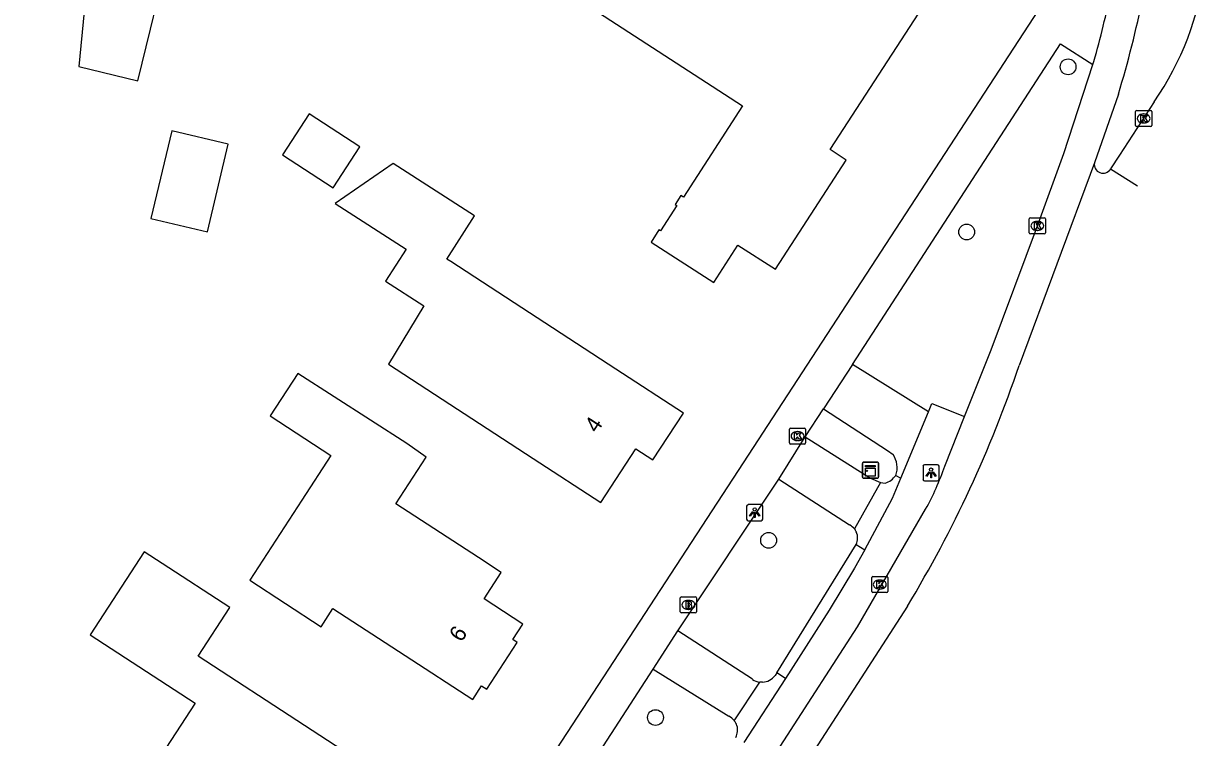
# Model space of a CAD drawing. Extents: x 161141 to 161601, y 381708 to 382245.
# Drawn here: x 161517.1 to 161590.2, y 382082.4 to 382126.6 of the extents above; entities that cross this region are included whole.
import ezdxf

# ---------------------------------------------------------------- set-up
doc = ezdxf.new("R2010")
doc.units = 0
for name, color, linetype in [('IMGEO_Boom', 7, 'Continuous'), ('IMGEO_Brandkraan', 7, 'Continuous'), ('IMGEO_Kast', 7, 'Continuous'), ('IMGEO_Kolk', 7, 'Continuous'), ('IMGEO_Lichtpunt', 7, 'Continuous'), ('IMGEO_Pand', 7, 'Continuous'), ('IMGEO_Pand_nummerreeks', 7, 'Continuous'), ('IMGEO_Parkeervlak_open', 7, 'Continuous'), ('IMGEO_Rijbaan_lokaal_gesloten', 7, 'Continuous'), ('IMGEO_Rijbaan_lokaal_open', 7, 'Continuous'), ('IMGEO_Voetpad_open', 7, 'Continuous')]:
    doc.layers.add(name, color=color, linetype=linetype)

msp = doc.modelspace()

# ---------------------------------------------------------------- linework, layer by layer
at = {"layer": 'IMGEO_Boom'}
for centre in [(161581.734, 382123.901), (161575.455, 382113.672), (161563.196, 382094.579), (161556.197, 382083.607)]:
    msp.add_circle(centre, 0.489, dxfattribs=at)
at = {"layer": 'IMGEO_Brandkraan'}
for p, q in [((161557.732, 382090.159), (161557.732, 382091.011)), ((161557.807, 382091.085), (161558.659, 382091.085)), ((161558.733, 382091.011), (161558.733, 382090.159)), ((161558.243, 382090.305), (161558.218, 382090.305)), ((161558.22, 382090.865), (161558.245, 382090.865)), ((161558.659, 382090.085), (161557.807, 382090.085))]:
    msp.add_line(p, q, dxfattribs=at)
for points in [[(161557.732, 382090.159), (161557.732, 382091.011)], [(161557.807, 382091.085), (161558.659, 382091.085)], [(161558.733, 382091.011), (161558.733, 382090.159)], [(161558.08, 382090.785), (161558.08, 382090.385), (161558.293, 382090.385)], [(161558.311, 382090.785), (161558.08, 382090.785)], [(161558.259, 382090.704), (161558.205, 382090.704), (161558.205, 382090.628)], [(161558.205, 382090.628), (161558.258, 382090.628)], [(161558.267, 382090.552), (161558.205, 382090.552), (161558.205, 382090.471)], [(161558.205, 382090.471), (161558.267, 382090.471)], [(161558.659, 382090.085), (161557.807, 382090.085)]]:
    msp.add_lwpolyline(points, dxfattribs=at)
for centre, radius, start, end in [((161557.809, 382091.009), 0.0765, 91.55205, 178.44795), ((161557.809, 382091.009), 0.0765, 91.55205, 178.44795), ((161558.657, 382091.009), 0.0765, 1.55205, 88.44795), ((161558.657, 382091.009), 0.0765, 1.55205, 88.44795), ((161557.809, 382090.161), 0.0765, 181.55205, 268.44795), ((161557.809, 382090.161), 0.0765, 181.55205, 268.44795), ((161558.26, 382090.666), 0.0379, 267.82845, 90.93552), ((161558.268, 382090.511), 0.0404, 269.87594, 90.50774), ((161558.299, 382090.636), 0.251, 268.66757, 293.53466), ((161558.315, 382090.64), 0.145, 59.4692, 91.53667), ((161558.34, 382090.687), 0.0922, 285.51372, 58.15012), ((161558.345, 382090.495), 0.105, 301.31148, 78.98903), ((161558.657, 382090.161), 0.0765, 271.55205, 358.44795), ((161558.657, 382090.161), 0.0765, 271.55205, 358.44795)]:
    msp.add_arc(centre, radius, start, end, dxfattribs=at)
for centre, major_axis, ratio, start_param, end_param in [((161558.219, 382090.585), (-0.387, 0.002), 0.722429, 4.712389, 7.853982), ((161558.244, 382090.585), (-0.39, 0.002), 0.717154, 1.570796, 4.712389)]:
    msp.add_ellipse(centre, major_axis=major_axis, ratio=ratio, start_param=start_param, end_param=end_param, dxfattribs=at)
at = {"layer": 'IMGEO_Kast'}
for p, q in [((161569.001, 382098.502), (161569.001, 382099.343)), ((161569.001, 382099.343), (161569.001, 382098.502)), ((161569.076, 382099.427), (161569.917, 382099.427)), ((161569.917, 382099.427), (161569.076, 382099.427)), ((161570.001, 382099.352), (161570.001, 382098.511)), ((161570.001, 382098.511), (161570.001, 382099.352)), ((161569.926, 382098.427), (161569.085, 382098.427)), ((161569.085, 382098.427), (161569.926, 382098.427))]:
    msp.add_line(p, q, dxfattribs=at)
for points in [[(161569.196, 382099.217), (161569.796, 382099.217), (161569.796, 382099.132), (161569.196, 382099.132), (161569.196, 382099.217)], [(161569.196, 382099.042), (161569.796, 382099.042), (161569.796, 382098.553), (161569.196, 382098.553), (161569.196, 382099.042)]]:
    msp.add_lwpolyline(points, dxfattribs=at)
msp.add_circle((161569.28, 382098.891), 0.0377, dxfattribs=at)
for centre, start, end in [((161569.079, 382099.349), 92.4484, 184.28452), ((161569.079, 382099.349), 92.4484, 184.28452), ((161569.923, 382099.349), 2.4484, 94.28452), ((161569.923, 382099.349), 2.4484, 94.28452), ((161569.079, 382098.505), 182.4484, 274.28452), ((161569.079, 382098.505), 182.4484, 274.28452), ((161569.923, 382098.505), 272.4484, 4.28452), ((161569.923, 382098.505), 272.4484, 4.28452)]:
    msp.add_arc(centre, 0.0779, start, end, dxfattribs=at)
at = {"layer": 'IMGEO_Kolk'}
for p, q in [((161585.911, 382120.277), (161585.911, 382121.129)), ((161585.986, 382121.203), (161586.838, 382121.203)), ((161586.399, 382120.983), (161586.424, 382120.983)), ((161586.912, 382121.129), (161586.912, 382120.277)), ((161586.838, 382120.203), (161585.986, 382120.203)), ((161586.422, 382120.423), (161586.397, 382120.423)), ((161579.331, 382113.627), (161579.331, 382114.479)), ((161579.406, 382114.553), (161580.258, 382114.553)), ((161579.819, 382114.333), (161579.844, 382114.333)), ((161580.332, 382114.479), (161580.332, 382113.627)), ((161580.258, 382113.553), (161579.406, 382113.553)), ((161579.842, 382113.773), (161579.817, 382113.773)), ((161564.487, 382100.61), (161564.487, 382101.462)), ((161564.562, 382101.536), (161565.414, 382101.536)), ((161564.975, 382101.316), (161565, 382101.316)), ((161565.488, 382101.462), (161565.488, 382100.61)), ((161565.414, 382100.536), (161564.562, 382100.536)), ((161564.998, 382100.756), (161564.973, 382100.756)), ((161569.652, 382092.345), (161570.504, 382092.345)), ((161569.577, 382091.419), (161569.577, 382092.271)), ((161570.065, 382092.125), (161570.09, 382092.125)), ((161570.578, 382092.271), (161570.578, 382091.419)), ((161570.504, 382091.345), (161569.652, 382091.345)), ((161570.088, 382091.565), (161570.063, 382091.565))]:
    msp.add_line(p, q, dxfattribs=at)
for points in [[(161585.911, 382120.277), (161585.911, 382121.129)], [(161585.986, 382121.203), (161586.838, 382121.203)], [(161586.232, 382120.903), (161586.355, 382120.903), (161586.355, 382120.752), (161586.485, 382120.903), (161586.649, 382120.903), (161586.503, 382120.752), (161586.656, 382120.503), (161586.504, 382120.503), (161586.419, 382120.667), (161586.355, 382120.6), (161586.355, 382120.503), (161586.232, 382120.503), (161586.232, 382120.903)], [(161586.912, 382121.129), (161586.912, 382120.277)], [(161586.838, 382120.203), (161585.986, 382120.203)], [(161579.331, 382113.627), (161579.331, 382114.479)], [(161579.406, 382114.553), (161580.258, 382114.553)], [(161580.332, 382114.479), (161580.332, 382113.627)], [(161580.258, 382113.553), (161579.406, 382113.553)], [(161579.652, 382114.253), (161579.775, 382114.253), (161579.775, 382114.102), (161579.905, 382114.253), (161580.069, 382114.253), (161579.923, 382114.102), (161580.076, 382113.853), (161579.924, 382113.853), (161579.839, 382114.017), (161579.775, 382113.95), (161579.775, 382113.853), (161579.652, 382113.853), (161579.652, 382114.253)], [(161564.487, 382100.61), (161564.487, 382101.462)], [(161564.562, 382101.536), (161565.414, 382101.536)], [(161564.808, 382101.236), (161564.931, 382101.236), (161564.931, 382101.085), (161565.061, 382101.236), (161565.225, 382101.236), (161565.079, 382101.085), (161565.232, 382100.836), (161565.08, 382100.836), (161564.995, 382101), (161564.931, 382100.933), (161564.931, 382100.836), (161564.808, 382100.836), (161564.808, 382101.236)], [(161565.488, 382101.462), (161565.488, 382100.61)], [(161565.414, 382100.536), (161564.562, 382100.536)], [(161569.652, 382092.345), (161570.504, 382092.345)], [(161569.577, 382091.419), (161569.577, 382092.271)], [(161569.898, 382092.045), (161570.021, 382092.045), (161570.021, 382091.894), (161570.151, 382092.045), (161570.315, 382092.045), (161570.169, 382091.894), (161570.322, 382091.645), (161570.17, 382091.645), (161570.085, 382091.809), (161570.021, 382091.742), (161570.021, 382091.645), (161569.898, 382091.645), (161569.898, 382092.045)], [(161570.578, 382092.271), (161570.578, 382091.419)], [(161570.504, 382091.345), (161569.652, 382091.345)]]:
    msp.add_lwpolyline(points, dxfattribs=at)
for centre, start, end in [((161585.988, 382121.127), 91.55205, 178.44795), ((161585.988, 382121.127), 91.55205, 178.44795), ((161586.836, 382121.127), 1.55205, 88.44795), ((161586.836, 382121.127), 1.55205, 88.44795), ((161585.988, 382120.279), 181.55205, 268.44795), ((161585.988, 382120.279), 181.55205, 268.44795), ((161586.836, 382120.279), 271.55205, 358.44795), ((161586.836, 382120.279), 271.55205, 358.44795), ((161579.408, 382114.477), 91.55205, 178.44795), ((161579.408, 382114.477), 91.55205, 178.44795), ((161580.256, 382114.477), 1.55205, 88.44795), ((161580.256, 382114.477), 1.55205, 88.44795), ((161579.408, 382113.629), 181.55205, 268.44795), ((161579.408, 382113.629), 181.55205, 268.44795), ((161580.256, 382113.629), 271.55205, 358.44795), ((161580.256, 382113.629), 271.55205, 358.44795), ((161564.564, 382101.46), 91.55205, 178.44795), ((161564.564, 382101.46), 91.55205, 178.44795), ((161565.412, 382101.46), 1.55205, 88.44795), ((161565.412, 382101.46), 1.55205, 88.44795), ((161564.564, 382100.612), 181.55205, 268.44795), ((161564.564, 382100.612), 181.55205, 268.44795), ((161565.412, 382100.612), 271.55205, 358.44795), ((161565.412, 382100.612), 271.55205, 358.44795), ((161569.654, 382092.269), 91.55205, 178.44795), ((161569.654, 382092.269), 91.55205, 178.44795), ((161570.502, 382092.269), 1.55205, 88.44795), ((161570.502, 382092.269), 1.55205, 88.44795), ((161569.654, 382091.421), 181.55205, 268.44795), ((161569.654, 382091.421), 181.55205, 268.44795), ((161570.502, 382091.421), 271.55205, 358.44795), ((161570.502, 382091.421), 271.55205, 358.44795)]:
    msp.add_arc(centre, 0.0765, start, end, dxfattribs=at)
for centre, major_axis, ratio, start_param, end_param in [((161586.398, 382120.703), (-0.387, 0.002), 0.722429, 4.712389, 7.853982), ((161586.423, 382120.703), (-0.39, 0.002), 0.717154, 1.570796, 4.712389), ((161579.818, 382114.053), (-0.387, 0.002), 0.722429, 4.712389, 7.853982), ((161579.843, 382114.053), (-0.39, 0.002), 0.717154, 1.570796, 4.712389), ((161564.974, 382101.036), (-0.387, 0.002), 0.722429, 4.712389, 7.853982), ((161564.999, 382101.036), (-0.39, 0.002), 0.717154, 1.570796, 4.712389), ((161570.064, 382091.845), (-0.387, 0.002), 0.722429, 4.712389, 7.853982), ((161570.089, 382091.845), (-0.39, 0.002), 0.717154, 1.570796, 4.712389)]:
    msp.add_ellipse(centre, major_axis=major_axis, ratio=ratio, start_param=start_param, end_param=end_param, dxfattribs=at)
at = {"layer": 'IMGEO_Lichtpunt'}
for p, q in [((161572.754, 382099.164), (161572.754, 382098.357)), ((161572.754, 382099.164), (161572.754, 382098.357)), ((161573.656, 382099.259), (161572.848, 382099.259)), ((161573.656, 382099.259), (161572.848, 382099.259)), ((161573.75, 382098.357), (161573.75, 382099.164)), ((161573.75, 382098.357), (161573.75, 382099.164)), ((161572.848, 382098.263), (161573.656, 382098.263)), ((161572.848, 382098.263), (161573.656, 382098.263)), ((161562.739, 382096.79), (161561.931, 382096.79)), ((161562.739, 382096.79), (161561.931, 382096.79)), ((161561.837, 382096.695), (161561.837, 382095.888)), ((161561.837, 382096.695), (161561.837, 382095.888)), ((161562.833, 382095.888), (161562.833, 382096.695)), ((161562.833, 382095.888), (161562.833, 382096.695)), ((161561.931, 382095.794), (161562.739, 382095.794)), ((161561.931, 382095.794), (161562.739, 382095.794))]:
    msp.add_line(p, q, dxfattribs=at)
for points in [[(161573.128, 382098.828), (161573.167, 382098.8), (161572.979, 382098.538), (161572.941, 382098.565), (161573.128, 382098.828)], [(161573.23, 382098.78), (161573.277, 382098.78), (161573.277, 382098.458), (161573.23, 382098.458), (161573.23, 382098.78)], [(161573.34, 382098.8), (161573.378, 382098.827), (161573.565, 382098.565), (161573.526, 382098.537), (161573.34, 382098.8)], [(161562.211, 382096.359), (161562.25, 382096.331), (161562.062, 382096.069), (161562.024, 382096.096), (161562.211, 382096.359)], [(161562.313, 382096.311), (161562.36, 382096.311), (161562.36, 382095.989), (161562.313, 382095.989), (161562.313, 382096.311)], [(161562.423, 382096.331), (161562.461, 382096.358), (161562.648, 382096.096), (161562.609, 382096.068), (161562.423, 382096.331)]]:
    msp.add_lwpolyline(points, dxfattribs=at)
for centre in [(161573.253, 382098.962), (161562.336, 382096.493)]:
    msp.add_circle(centre, 0.0994, dxfattribs=at)
for centre, start, end in [((161572.848, 382099.164), 90, 180), ((161572.848, 382099.164), 90, 180), ((161573.656, 382099.164), 0, 90), ((161573.656, 382099.164), 0, 90), ((161572.848, 382098.357), 180, 270), ((161572.848, 382098.357), 180, 270), ((161573.656, 382098.357), 270, 0), ((161573.656, 382098.357), 270, 360), ((161561.931, 382096.695), 90, 180), ((161561.931, 382096.695), 90, 180), ((161562.739, 382096.695), 0, 90), ((161562.739, 382096.695), 0, 90), ((161561.931, 382095.888), 180, 270), ((161561.931, 382095.888), 180, 270), ((161562.739, 382095.888), 270, 0), ((161562.739, 382095.888), 270, 360)]:
    msp.add_arc(centre, 0.0946, start, end, dxfattribs=at)
at = {"layer": 'IMGEO_Pand'}
for points in [[(161517.083, 382131.744), (161521.155, 382130.743), (161520.5, 382123.927), (161524.147, 382123.029), (161524.932, 382126.234), (161526.122, 382131.09), (161525.15, 382131.328), (161527.844, 382142.322), (161524.397, 382143.169), (161524.565, 382143.853), (161520.683, 382144.806), (161520.515, 382144.122), (161520.139, 382144.214)], [(161549.327, 382129.461), (161561.573, 382121.485), (161557.928, 382115.823), (161557.772, 382115.923), (161557.423, 382115.381), (161557.516, 382115.321), (161556.497, 382113.739), (161556.405, 382113.798), (161555.917, 382113.042), (161559.803, 382110.542), (161561.29, 382112.864), (161563.616, 382111.372), (161568.005, 382118.131), (161567.013, 382118.771), (161572.764, 382127.628)], [(161533.101, 382118.442), (161536.243, 382116.402), (161537.895, 382118.945), (161534.754, 382120.986), (161533.101, 382118.442)], [(161529.748, 382119.108), (161526.247, 382119.94), (161524.957, 382114.51), (161528.458, 382113.678), (161529.748, 382119.108)], [(161548.616, 382099.647), (161552.805, 382096.917), (161554.976, 382100.25), (161556.035, 382099.56), (161557.924, 382102.459), (161553.735, 382105.188), (161543.522, 382111.842), (161543.277, 382111.999), (161544.995, 382114.67), (161539.948, 382117.916), (161536.361, 382115.445), (161540.764, 382112.614), (161539.49, 382110.634), (161541.863, 382109.109), (161539.661, 382105.481), (161548.616, 382099.647)], [(161542.007, 382099.725), (161540.81, 382100.569), (161534.048, 382104.912), (161532.334, 382102.281), (161536.104, 382099.824), (161534.302, 382097.059), (161531.076, 382092.108), (161535.491, 382089.231), (161536.228, 382090.362), (161540.691, 382087.454), (161544.88, 382084.724), (161545.435, 382085.575), (161545.753, 382085.367), (161547.633, 382088.253), (161547.357, 382088.433), (161547.984, 382089.396), (161545.581, 382090.962), (161546.648, 382092.599), (161545.242, 382093.515), (161540.131, 382096.846), (161542.007, 382099.725)], [(161525.007, 382080.354), (161529.353, 382077.522), (161528.63, 382076.412), (161532.059, 382074.178), (161532.764, 382075.259), (161536.96, 382072.525), (161541.06, 382078.818), (161527.88, 382087.405), (161529.841, 382090.414), (161525.651, 382093.143), (161524.545, 382093.864), (161521.198, 382088.726), (161527.701, 382084.489), (161525.007, 382080.354)]]:
    msp.add_lwpolyline(points, dxfattribs=at)
at = {"layer": 'IMGEO_Parkeervlak_open'}
msp.add_lwpolyline([(161573.086, 382102.543), (161573.302, 382103.064), (161575.329, 382102.253)], dxfattribs=at)
at = {"layer": 'IMGEO_Rijbaan_lokaal_gesloten'}
for points in [[(161575.329, 382102.253), (161576.98, 382106.377), (161579.832, 382114.053), (161581.47, 382118.537), (161583.268, 382124.041)], [(161583.268, 382124.041), (161583.333, 382124.239)], [(161584.845, 382122.205), (161583.363, 382117.958)], [(161587.065, 382121.731), (161584.91, 382118.432), (161584.369, 382117.575)], [(161583.363, 382117.958), (161578.708, 382105.416)], [(161584.369, 382117.575), (161586.04, 382116.528), (161586.04, 382116.528)], [(161574.099, 382099.179), (161575.329, 382102.253)], [(161534.744, 382036.848), (161535.916, 382038.476), (161568.691, 382089.227), (161572.916, 382096.506)], [(161571.794, 382090.515), (161536.35, 382035.66)]]:
    msp.add_lwpolyline(points, dxfattribs=at)
for centre, radius, start, end in [((161571.45, 382132.448), 18.939, 325.53522, 352.61152), ((161536.078, 382137.935), 49.199, 343.83692, 349.09958), ((161526.101, 382140.245), 61.452, 342.92824, 348.73123), ((161507.44, 382129.429), 75.205, 328.83886, 341.37895), ((161558.542, 382104.466), 16.43, 331.02362, 341.23052)]:
    msp.add_arc(centre, radius, start, end, dxfattribs=at)
at = {"layer": 'IMGEO_Rijbaan_lokaal_open'}
msp.add_arc((161583.903, 382117.864), 0.548, 170.16781, 328.14696, dxfattribs=at)
at = {"layer": 'IMGEO_Voetpad_open'}
for points in [[(161581.409, 382129.761), (161561.628, 382099.383), (161523.437, 382040.853)], [(161568.38, 382105.476), (161581.267, 382125.334), (161583.268, 382124.041)], [(161568.38, 382105.476), (161566.592, 382102.722)], [(161573.086, 382102.543), (161568.38, 382105.476)], [(161565.463, 382100.982), (161566.592, 382102.722)], [(161566.592, 382102.722), (161570.551, 382100.153), (161570.897, 382099.892)], [(161571.379, 382098.431), (161573.086, 382102.543)], [(161563.831, 382098.367), (161565.463, 382100.982)], [(161565.463, 382100.982), (161569.51, 382098.421), (161570.115, 382098.159)], [(161557.579, 382088.971), (161563.831, 382098.367)], [(161563.831, 382098.367), (161568.212, 382095.532)], [(161569.158, 382093.992), (161570.865, 382097.191), (161571.379, 382098.431)], [(161571.074, 382098.605), (161571.379, 382098.431)], [(161570.115, 382098.159), (161568.514, 382095.286)], [(161570.115, 382098.159), (161570.416, 382098.113)], [(161563.702, 382086.387), (161568.611, 382094.325)], [(161569.158, 382093.992), (161568.512, 382092.854), (161566.951, 382090.262), (161564.239, 382086.032)], [(161568.611, 382094.325), (161569.158, 382093.992)], [(161556.061, 382086.613), (161557.579, 382088.971)], [(161562.195, 382085.975), (161557.579, 382088.971)], [(161549.678, 382076.751), (161556.061, 382086.613)], [(161556.061, 382086.613), (161560.731, 382083.685)], [(161561.075, 382083.414), (161562.648, 382085.805)], [(161564.239, 382086.032), (161561.667, 382082.065)], [(161562.819, 382085.798), (161562.648, 382085.805)], [(161563.702, 382086.387), (161563.596, 382086.216)], [(161564.239, 382086.032), (161563.702, 382086.387)]]:
    msp.add_lwpolyline(points, dxfattribs=at)
for centre, radius, start, end in [((161569.741, 382099.077), 1.414, 340.48835, 35.17308), ((161569.9, 382099.489), 1.469, 290.54939, 323.02303), ((161567.826, 382094.75), 0.872, 37.93195, 63.73762), ((161567.819, 382094.73), 0.89, 24.7571, 38.63242), ((161567.803, 382094.731), 0.904, 333.32683, 24.31686), ((161562.771, 382086.822), 1.025, 235.774, 263.0862), ((161562.77, 382086.82), 1.023, 272.73451, 323.82302), ((161560.341, 382082.836), 0.935, 38.2235, 65.31507), ((161560.326, 382082.82), 0.956, 17.67097, 38.43487), ((161560.344, 382082.836), 0.935, 330.87903, 17.06204)]:
    msp.add_arc(centre, radius, start, end, dxfattribs=at)

# ---------------------------------------------------------------- texts
at = {"layer": 'IMGEO_Pand_nummerreeks'}
for s, rotation, p in [('4', 56.92118, (161552.573, 382101.177)), ('6', 56.40059, (161544.181, 382088.225))]:
    msp.add_text(s, height=1, rotation=rotation, dxfattribs=at).set_placement(p)

doc.saveas('drawing.dxf')
